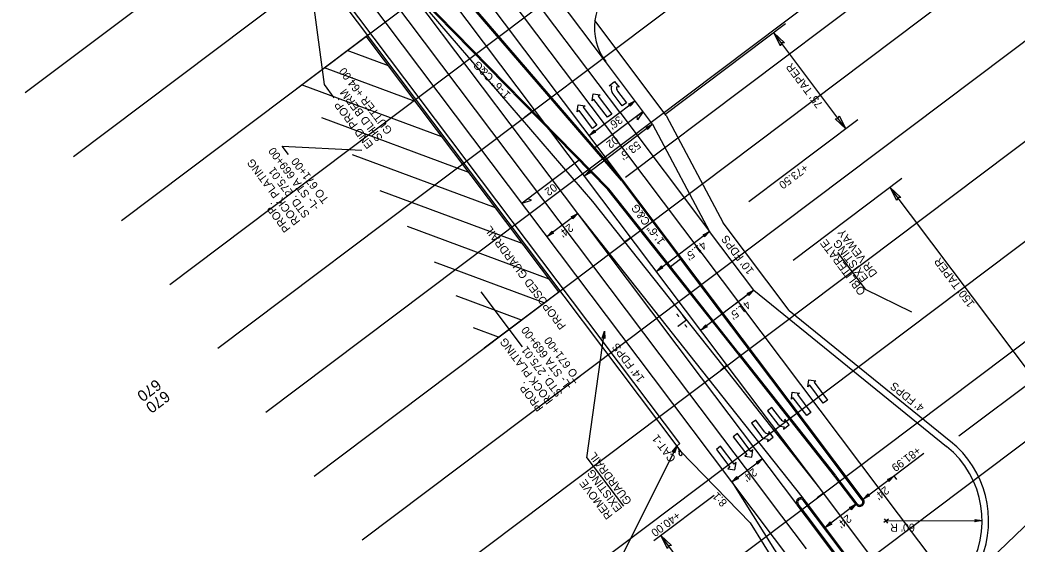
# Model space of a CAD drawing. Extents: x 1262309 to 1264352, y 775189 to 777755.
# Drawn here: x 1263383 to 1264006, y 775861 to 776189 of the extents above; entities that cross this region are included whole.
import ezdxf

# ---------------------------------------------------------------- set-up
doc = ezdxf.new("R2010")
doc.units = 0
for name, color, linetype in [('Default', 7, 'Continuous'), ('Prop Conc 1ft 6in Curb and Gutter', 7, 'Continuous'), ('Prop Conc 5in Monolithic Keyed In Island', 7, 'Continuous'), ('Prop Conc Shoulder Berm Gutter', 7, 'Continuous'), ('Prop Dimension', 7, 'Continuous'), ('Prop Dimension Text', 7, 'Continuous'), ('Prop EOT', 7, 'Continuous'), ('Prop Geotechnical Rock Plating', 7, 'Continuous'), ('Prop Guardrail', 7, 'Continuous'), ('Prop Guardrail Anchor Unit CELL', 7, 'Continuous'), ('Prop Horizontal Alignment', 7, 'Continuous'), ('Prop Horizontal Alignment Station Label', 7, 'Continuous'), ('Prop Horizontal Alignment Tick Label', 7, 'Continuous'), ('Prop Horizontal Alignment Tick Large', 7, 'Continuous'), ('Prop Horizontal Alignment Tick Small', 7, 'Continuous'), ('Prop Lane Arrow CELL', 7, 'Continuous'), ('Prop Lane Lines', 7, 'Continuous'), ('Prop Paved Shoulder', 7, 'Continuous'), ('Prop Superelevation  Arrow CELL', 7, 'Continuous'), ('Prop Superelevation Label', 7, 'Continuous'), ('Prop Terminator CELL', 7, 'Continuous'), ('Scratch_Level_3', 7, 'Continuous')]:
    doc.layers.add(name, color=color, linetype=linetype)

msp = doc.modelspace()

# ---------------------------------------------------------------- linework, layer by layer
at = {"layer": 'Default'}
for p, q in [((1263704.74, 776132.85), (1263704.74, 776132.85)), ((1263704.74, 776132.85), (1263704.74, 776132.85)), ((1263764.91, 776052.98), (1263764.91, 776052.98)), ((1263764.91, 776052.98), (1263764.91, 776052.98)), ((1263825.07, 775973.1), (1263825.07, 775973.1)), ((1263825.07, 775973.1), (1263825.07, 775973.1)), ((1263792.88, 775922.07), (1263793.52, 775922.55)), ((1263793.3, 775921.51), (1263792.88, 775922.07)), ((1263793.94, 775922), (1263792.88, 775922.07)), ((1263793.52, 775922.55), (1263793.3, 775921.51)), ((1263793.94, 775922), (1263793.3, 775921.51)), ((1263793.52, 775922.55), (1263795.65, 775919.72)), ((1263793.52, 775922.55), (1263793.94, 775922)), ((1263795.28, 775919.55), (1263794.46, 775921.31)), ((1263794.75, 775919.59), (1263795.39, 775920.07)), ((1263795.17, 775919.03), (1263794.75, 775919.59)), ((1263795.81, 775919.51), (1263794.75, 775919.59)), ((1263794.94, 775918.03), (1263795.25, 775919.09)), ((1263795.39, 775920.07), (1263795.17, 775919.03)), ((1263795.81, 775919.51), (1263795.17, 775919.03)), ((1263795.39, 775920.07), (1263795.81, 775919.51)), ((1263795.73, 775919.62), (1263795.65, 775919.72)), ((1263795.65, 775919.72), (1263796.69, 775918.35)), ((1263885.24, 775893.22), (1263885.24, 775893.22)), ((1263885.24, 775893.22), (1263885.24, 775893.22))]:
    msp.add_line(p, q, dxfattribs=at)
msp.add_ellipse((1263795.89, 775917.75), major_axis=(0.793, 0.597), ratio=0.995379, start_param=2.210226, end_param=6.283185, dxfattribs=at)
at = {"layer": 'Prop Conc 1ft 6in Curb and Gutter'}
for p, q in [((1263759.04, 776088.61), (1263638.31, 776228.96)), ((1263751.03, 776083.43), (1263620.92, 776216.3)), ((1263759.04, 776088.61), (1263795.92, 776039.64)), ((1263789.59, 776034.75), (1263751.03, 776083.43))]:
    msp.add_line(p, q, dxfattribs=at)
at = {"layer": 'Prop Conc 5in Monolithic Keyed In Island'}
for p, q in [((1263789.59, 776034.75), (1263795.92, 776039.64)), ((1263852.24, 775964.87), (1263795.93, 776039.64)), ((1263832.41, 775980.69), (1263789.6, 776034.75)), ((1263892.99, 775904.15), (1263832.43, 775980.69)), ((1263873.97, 775936.02), (1263852.24, 775964.87)), ((1263909.45, 775888.91), (1263873.97, 775936.02)), ((1263906.27, 775886.51), (1263893, 775904.13)), ((1263913.22, 775834.88), (1263872.6, 775888.8)), ((1263875.17, 775878.75), (1263869.42, 775886.39)), ((1263909.06, 775886.13), (1263909.04, 775886.11)), ((1263932.02, 775803.27), (1263875.17, 775878.75))]:
    msp.add_line(p, q, dxfattribs=at)
for centre, radius, start, end in [((1263871.04, 775887.55), 2, 38.65311, 215.6082), ((1263907.87, 775887.7), 1.99, 216.35497, 36.98742)]:
    msp.add_arc(centre, radius, start, end, dxfattribs=at)
at = {"layer": 'Prop Conc Shoulder Berm Gutter'}
for p, q in [((1263560.24, 776232.45), (1263699.52, 776047.54)), ((1263699.52, 776047.54), (1263793.48, 775922.63))]:
    msp.add_line(p, q, dxfattribs=at)
at = {"layer": 'Prop Dimension'}
for p, q in [((1263934.61, 776220.85), (1263761.55, 776090.5)), ((1263861.48, 776186.44), (1263786.12, 776129.67)), ((1263899.19, 776120.94), (1263854.09, 776180.87)), ((1263906.61, 776126.53), (1263838.59, 776075.3)), ((1263934.25, 776089.82), (1263866.24, 776038.59)), ((1264017.09, 775964.42), (1263926.84, 776084.24)), ((1263894, 776043.66), (1263911.23, 776020.7)), ((1263911.23, 776020.7), (1263940.1, 776006.46)), ((1264024.5, 775970.01), (1263969.69, 775928.73)), ((1264095.35, 775953.43), (1263984.45, 775847.18)), ((1263828.02, 775900.2), (1263847.19, 775914.64)), ((1263816.85, 775891.79), (1263779.23, 775863.45)), ((1263924.36, 775875.82), (1263923, 775874.79)), ((1263924.36, 775875.82), (1263923.33, 775877.18)), ((1263925.73, 775876.85), (1263924.36, 775875.82)), ((1263924.36, 775875.82), (1263984.36, 775876.02)), ((1263925.39, 775874.45), (1263924.36, 775875.82)), ((1263867.83, 775754.67), (1263783.48, 775866.65))]:
    msp.add_line(p, q, dxfattribs=at)
for points in [[(1263742.82, 776118.87), (1263738.77, 776116.76), (1263741.89, 776120.14), (1263741.92, 776119.15)], [(1263739.93, 776093.62), (1263735.88, 776091.52), (1263739, 776094.89), (1263739.03, 776093.91)], [(1263716.56, 776055.67), (1263712.51, 776053.56), (1263715.63, 776056.94), (1263715.66, 776055.95)], [(1263784.9, 776033.92), (1263780.85, 776031.81), (1263783.97, 776035.18), (1263784, 776034.2)], [(1263812.56, 775997.19), (1263808.5, 775995.1), (1263811.63, 775998.46), (1263811.65, 775997.48)], [(1263914.02, 775891.58), (1263909.97, 775889.47), (1263913.09, 775892.85), (1263913.11, 775891.86)], [(1263890.39, 775873.92), (1263886.34, 775871.82), (1263889.45, 775875.19), (1263889.48, 775874.21)]]:
    msp.add_lwpolyline(points, close=True, dxfattribs=at)
at = {"layer": 'Prop Dimension Text'}
for p, q in [((1263573.35, 776148.51), (1263562.13, 776233.92)), ((1263579.58, 776140.3), (1263573.35, 776148.51)), ((1263738.77, 776116.76), (1263767.53, 776138.42)), ((1263778.46, 776123.9), (1263735.88, 776091.52)), ((1263551.05, 776104.85), (1263547.06, 776110.14)), ((1263547.06, 776110.14), (1263596.68, 776107.56)), ((1263731.68, 776068), (1263712.51, 776053.56)), ((1263814, 776056.77), (1263780.85, 776031.81)), ((1263697.25, 775984.73), (1263671.36, 776018.93)), ((1263839.65, 776018.57), (1263808.5, 775995.1)), ((1263841.65, 776020.07), (1263829.72, 776011.09)), ((1263737.43, 775915.28), (1263748.39, 775994.46)), ((1263793.48, 775922.63), (1263759.14, 775854)), ((1263909.97, 775889.47), (1263947.96, 775918.09)), ((1263737.43, 775915.28), (1263760.26, 775884.99)), ((1263929.07, 775904), (1263930.72, 775901.82)), ((1263905.51, 775886.26), (1263886.34, 775871.82))]:
    msp.add_line(p, q, dxfattribs=at)
for points in [[(1263858.27, 776172.75), (1263854.09, 776180.87), (1263860.82, 776174.6), (1263858.85, 776174.56)], [(1263763.48, 776136.31), (1263767.53, 776138.42), (1263764.41, 776135.04), (1263764.39, 776136.03)], [(1263774.41, 776121.8), (1263778.46, 776123.9), (1263775.35, 776120.53), (1263775.32, 776121.51)], [(1263895.02, 776129.07), (1263899.19, 776120.94), (1263892.47, 776127.21), (1263894.44, 776127.25)], [(1263895.02, 776129.07), (1263899.19, 776120.94), (1263892.47, 776127.21), (1263894.44, 776127.25)], [(1263931.02, 776076.12), (1263926.84, 776084.24), (1263933.56, 776077.98), (1263931.59, 776077.93)], [(1263727.63, 776065.89), (1263731.68, 776068), (1263728.57, 776064.62), (1263728.54, 776065.61)], [(1263809.95, 776054.67), (1263814, 776056.78), (1263810.88, 776053.4), (1263810.86, 776054.38)], [(1263837.59, 776017.98), (1263841.65, 776020.07), (1263838.51, 776016.71), (1263838.49, 776017.7)], [(1263844.06, 775911.32), (1263847.19, 775914.64), (1263843.1, 775912.56), (1263844.04, 775912.27)], [(1263832.08, 775902.29), (1263828.02, 775900.2), (1263831.16, 775903.57), (1263831.18, 775902.58)], [(1263925.09, 775901.81), (1263929.14, 775903.91), (1263926.02, 775900.54), (1263926, 775901.52)], [(1263901.46, 775884.15), (1263905.51, 775886.26), (1263902.39, 775882.88), (1263902.36, 775883.87)], [(1263787.66, 775858.53), (1263783.48, 775866.65), (1263790.2, 775860.39), (1263788.23, 775860.34)]]:
    msp.add_lwpolyline(points, close=True, dxfattribs=at)
at = {"layer": 'Prop EOT'}
for p, q in [((1263710.7, 776055.96), (1263423.46, 776437.32)), ((1263759.64, 776089.06), (1263638.9, 776229.42)), ((1263750.5, 776082.9), (1263620.38, 776215.77)), ((1263778.46, 776123.9), (1263749.05, 776162.96)), ((1263778.46, 776123.9), (1263814, 776056.78)), ((1263852.84, 775965.32), (1263759.64, 776089.06)), ((1263831.82, 775980.22), (1263750.5, 776082.9)), ((1263778.98, 775965.32), (1263710.7, 776055.96)), ((1263841.65, 776020.07), (1263814, 776056.78)), ((1263841.65, 776020.07), (1263962.14, 775922.43)), ((1263892.39, 775903.67), (1263831.83, 775980.21)), ((1263828.02, 775900.2), (1263778.98, 775965.32)), ((1263874.57, 775936.47), (1263852.84, 775965.32)), ((1263910.05, 775889.36), (1263874.57, 775936.47)), ((1263828.02, 775900.2), (1263902.67, 775781.16)), ((1263905.66, 775886.06), (1263892.39, 775903.67)), ((1263874.57, 775887.44), (1263873.2, 775889.25)), ((1263913.82, 775835.33), (1263874.57, 775887.44)), ((1263874.57, 775878.3), (1263868.82, 775885.94)), ((1263931.42, 775802.82), (1263874.57, 775878.3))]:
    msp.add_line(p, q, dxfattribs=at)
for centre, radius, start, end in [((1263777.07, 776183.93), 35, 127.94574, 216.98742), ((1263924.36, 775875.82), 60, 327.25458, 50.98263), ((1263871.01, 775887.59), 2.75, 126.98742, 216.98742), ((1263871.01, 775887.6), 2.74, 36.98742, 126.98742), ((1263907.86, 775887.72), 2.74, 306.98742, 36.98742), ((1263907.85, 775887.7), 2.74, 216.98742, 306.98742)]:
    msp.add_arc(centre, radius, start, end, dxfattribs=at)
at = {"layer": 'Prop Geotechnical Rock Plating'}
for p, q in [((1263556.16, 776146.13), (1263599.45, 776178.74)), ((1263719.76, 776018.97), (1263599.45, 776178.74)), ((1263613.36, 776160.26), (1263587.62, 776169.82)), ((1263630.08, 776138.05), (1263573.39, 776159.11)), ((1263646.81, 776115.84), (1263559.16, 776148.39)), ((1263663.54, 776093.63), (1263571.7, 776127.73)), ((1263680.26, 776071.42), (1263591.01, 776104.56)), ((1263696.99, 776049.21), (1263608.14, 776082.2)), ((1263713.72, 776026.99), (1263625.22, 776059.85)), ((1263710.67, 776012.12), (1263642.25, 776037.53)), ((1263673.29, 775983.97), (1263719.76, 776018.97)), ((1263696.44, 776001.41), (1263655.62, 776016.56)), ((1263682.13, 775990.72), (1263666.48, 775996.53))]:
    msp.add_line(p, q, dxfattribs=at)
at = {"layer": 'Prop Guardrail'}
for p, q in [((1263502.31, 776309.36), (1263699.52, 776047.54)), ((1263699.52, 776047.54), (1263793.48, 775922.63))]:
    msp.add_line(p, q, dxfattribs=at)
at = {"layer": 'Prop Horizontal Alignment'}
for p, q in [((1263830.93, 775965.32), (1263334.24, 776624.75)), ((1263874.57, 775907.39), (1263830.93, 775965.32)), ((1264143.94, 775549.75), (1263874.57, 775907.39))]:
    msp.add_line(p, q, dxfattribs=at)
at = {"layer": 'Prop Horizontal Alignment Tick Large'}
msp.add_line((1263704.74, 776132.85), (1263698.35, 776128.04), dxfattribs=at)
at = {"layer": 'Prop Horizontal Alignment Tick Small'}
for p, q in [((1263764.91, 776052.98), (1263760.92, 776049.97)), ((1263825.07, 775973.1), (1263821.08, 775970.09)), ((1263885.23, 775893.22), (1263881.24, 775890.22))]:
    msp.add_line(p, q, dxfattribs=at)
at = {"layer": 'Prop Lane Arrow CELL'}
for p, q in [((1263751.24, 776147.83), (1263754.73, 776150.52)), ((1263754.73, 776150.52), (1263757.47, 776146.95)), ((1263740.62, 776138.42), (1263741.2, 776142.8)), ((1263741.2, 776142.8), (1263745.65, 776142.21)), ((1263752.71, 776147.62), (1263751.24, 776147.83)), ((1263759.46, 776135.18), (1263753.11, 776143.61)), ((1263757.47, 776146.95), (1263756, 776147.16)), ((1263756.59, 776144.47), (1263762.09, 776137.16)), ((1263741.82, 776139.32), (1263740.62, 776138.42)), ((1263750.24, 776128.14), (1263741.82, 776139.32)), ((1263745.65, 776142.21), (1263744.46, 776141.31)), ((1263744.46, 776141.31), (1263752.88, 776130.12)), ((1263762.09, 776137.16), (1263759.46, 776135.18)), ((1263731.28, 776131.48), (1263731.86, 776135.86)), ((1263732.47, 776132.38), (1263731.28, 776131.48)), ((1263731.86, 776135.86), (1263736.31, 776135.27)), ((1263740.9, 776121.2), (1263732.47, 776132.38)), ((1263736.31, 776135.27), (1263735.11, 776134.37)), ((1263735.11, 776134.37), (1263743.53, 776123.18)), ((1263752.88, 776130.12), (1263750.24, 776128.14)), ((1263743.53, 776123.18), (1263740.9, 776121.2)), ((1263875.48, 775959.7), (1263876.06, 775964.09)), ((1263876.06, 775964.09), (1263880.51, 775963.49)), ((1263880.51, 775963.49), (1263879.32, 775962.59)), ((1263879.32, 775962.59), (1263887.74, 775951.41)), ((1263865.13, 775951.91), (1263865.71, 775956.29)), ((1263865.71, 775956.29), (1263870.16, 775955.7)), ((1263870.16, 775955.7), (1263868.96, 775954.79)), ((1263876.68, 775960.61), (1263875.48, 775959.7)), ((1263885.1, 775949.42), (1263876.68, 775960.61)), ((1263866.33, 775952.81), (1263865.13, 775951.91)), ((1263874.75, 775941.63), (1263866.33, 775952.81)), ((1263868.96, 775954.79), (1263877.39, 775943.61)), ((1263887.74, 775951.41), (1263885.1, 775949.42)), ((1263852.94, 775946.67), (1263850.31, 775944.68)), ((1263850.31, 775944.68), (1263856.65, 775936.26)), ((1263858.45, 775939.36), (1263852.94, 775946.67)), ((1263877.39, 775943.61), (1263874.75, 775941.63)), ((1263842.87, 775938.91), (1263840.23, 775936.92)), ((1263840.23, 775936.92), (1263846.58, 775928.5)), ((1263848.38, 775931.6), (1263842.87, 775938.91)), ((1263861.08, 775939.53), (1263860.87, 775938.06)), ((1263863.74, 775935.9), (1263861.08, 775939.53)), ((1263851.01, 775931.77), (1263850.8, 775930.3)), ((1263853.67, 775928.14), (1263851.01, 775931.77)), ((1263860.2, 775933.29), (1263863.74, 775935.9)), ((1263860.41, 775934.77), (1263860.2, 775933.29)), ((1263831.42, 775930.46), (1263828.78, 775928.47)), ((1263828.78, 775928.47), (1263837.21, 775917.29)), ((1263839.84, 775919.28), (1263831.42, 775930.46)), ((1263850.13, 775925.53), (1263853.67, 775928.14)), ((1263850.33, 775927), (1263850.13, 775925.53)), ((1263820.95, 775922.57), (1263818.31, 775920.58)), ((1263818.31, 775920.58), (1263826.73, 775909.4)), ((1263829.37, 775911.39), (1263820.95, 775922.57)), ((1263841.04, 775920.18), (1263839.84, 775919.28)), ((1263840.38, 775915.74), (1263841.04, 775920.18)), ((1263830.57, 775912.29), (1263829.37, 775911.39)), ((1263829.91, 775907.85), (1263830.57, 775912.29)), ((1263837.21, 775917.29), (1263836.01, 775916.39)), ((1263836.01, 775916.39), (1263840.38, 775915.74)), ((1263826.73, 775909.4), (1263825.53, 775908.5)), ((1263825.53, 775908.5), (1263829.91, 775907.85))]:
    msp.add_line(p, q, dxfattribs=at)
for centre, radius, start, end in [((1263757.72, 776146.09), 5.25, 162.99965, 208.31134), ((1263759.18, 776146.44), 3.27, 167.32924, 216.98742), ((1263861.06, 775941.31), 3.27, 216.98742, 266.64559), ((1263850.98, 775933.55), 3.27, 216.98742, 266.64559), ((1263860.31, 775940), 5.25, 225.66349, 270.97518), ((1263850.24, 775932.24), 5.25, 225.66349, 270.97518)]:
    msp.add_arc(centre, radius, start, end, dxfattribs=at)
at = {"layer": 'Prop Lane Lines'}
for p, q in [((1263794, 775965.32), (1263433.04, 776444.54)), ((1263749.05, 776162.96), (1263688.78, 776242.97)), ((1263759.64, 776089.06), (1263648.34, 776236.82)), ((1263757.94, 776131.2), (1263685.9, 776226.85)), ((1263748.36, 776123.98), (1263676.32, 776219.63)), ((1263731.68, 776068), (1263620.38, 776215.77)), ((1263741.09, 776075.45), (1263620.38, 776215.77)), ((1263757.94, 776131.2), (1263814, 776056.78)), ((1263968.96, 775831.09), (1263748.36, 776123.98)), ((1263822.42, 775972.77), (1263741.09, 776075.45)), ((1263809.02, 775965.32), (1263731.68, 776068)), ((1263882.89, 775896.34), (1263822.42, 775972.77)), ((1263836.43, 775908.99), (1263794, 775965.32)), ((1263868.55, 775886.29), (1263809.02, 775965.32)), ((1263859.23, 775878.72), (1263836.43, 775908.99)), ((1263871.74, 775842.16), (1263828.02, 775900.2)), ((1263896.07, 775878.84), (1263882.89, 775896.34)), ((1263874.57, 775858.35), (1263859.23, 775878.72))]:
    msp.add_line(p, q, dxfattribs=at)
for points in [[(1263813.01, 775965.32), (1263731.68, 776068)], [(1263872.65, 775889.93), (1263813.01, 775965.32)]]:
    msp.add_lwpolyline(points, dxfattribs=at)
at = {"layer": 'Prop Paved Shoulder'}
for p, q in [((1263795.48, 775924.14), (1263562.13, 776233.92)), ((1263786.93, 776129.29), (1263742.3, 776188.54)), ((1263786.93, 776129.29), (1263822.47, 776062.16)), ((1263863.82, 776007.25), (1263822.47, 776062.16)), ((1263863.82, 776007.25), (1263964.66, 775925.54)), ((1263795.48, 775924.14), (1263793.48, 775922.63)), ((1263795.81, 775919.51), (1263839.29, 775874.67)), ((1263839.29, 775874.67), (1263899.47, 775778.75))]:
    msp.add_line(p, q, dxfattribs=at)
msp.add_arc((1263924.36, 775875.82), 64, 337.81209, 50.98071, dxfattribs=at)
at = {"layer": 'Prop Superelevation  Arrow CELL'}
for p, q in [((1263772.56, 776131.74), (1263742.44, 776109.05)), ((1263732.56, 776101.22), (1263696.86, 776074.34))]:
    msp.add_line(p, q, dxfattribs=at)
for points in [[(1263772.56, 776131.74), (1263768.97, 776126.53), (1263768.87, 776128.95)], [(1263696.86, 776074.34), (1263702.86, 776076.35), (1263700.56, 776077.12)]]:
    msp.add_lwpolyline(points, close=True, dxfattribs=at)
at = {"layer": 'Prop Terminator CELL'}
for points in [[(1263747, 775990.11), (1263748.39, 775994.46), (1263748.56, 775989.87), (1263747.85, 775990.55)], [(1263790.74, 775918.98), (1263793.49, 775922.62), (1263792.12, 775918.23), (1263791.68, 775919.11)], [(1263979.86, 775876.78), (1263984.36, 775876.02), (1263979.84, 775875.21), (1263980.41, 775876.01)]]:
    msp.add_lwpolyline(points, close=True, dxfattribs=at)
at = {"layer": 'Scratch_Level_3'}
for p, q in [((1263386.48, 776143.52), (1263881.58, 776516.43)), ((1263416.56, 776103.58), (1263911.66, 776476.49)), ((1263446.64, 776063.64), (1263941.74, 776436.56)), ((1263476.73, 776023.7), (1263971.83, 776396.62)), ((1263506.81, 775983.76), (1264001.91, 776356.68)), ((1263536.89, 775943.83), (1264031.99, 776316.74)), ((1263566.97, 775903.89), (1264062.07, 776276.8)), ((1263597.05, 775863.95), (1264092.15, 776236.86)), ((1263627.14, 775824.01), (1264122.24, 776196.93)), ((1263657.22, 775784.07), (1264152.32, 776156.99)), ((1263687.3, 775744.13), (1264182.4, 776117.05)), ((1263717.38, 775704.2), (1264212.48, 776077.11))]:
    msp.add_line(p, q, dxfattribs=at)

# ---------------------------------------------------------------- texts
at = {"layer": 'Prop Dimension'}
msp.add_text('1\'-6" C&G', height=5, rotation=134.22343, dxfattribs=at).set_placement((1263690.1, 776142.54))
at = {"layer": 'Prop Dimension Text'}
for s, rotation, p in [("75' TAPER", 126.98742, (1263885.08, 776136.24)), ('GUTTER +64.00', 126.98742, (1263616.15, 776119.79)), ('SHLD BERM', 126.98742, (1263610.16, 776115.28)), ('END PROP.', 126.98742, (1263604.17, 776110.77)), ("36'", 217.25838, (1263757.35, 776129.34)), ("53.5'", 217.25838, (1263768.67, 776113.6)), ('-L- STA 669+00', 126.98742, (1263570.48, 776072.03)), ('ROCK PLATING', 126.98742, (1263558.49, 776063)), ('TO 671+00', 126.98742, (1263576.47, 776076.54)), ('STD. 275.01', 126.98742, (1263564.49, 776067.51)), ('+73.50', 216.98742, (1263873.33, 776099.29)), ('PROP.', 126.98742, (1263552.5, 776058.49)), ('1\'-6" C&G', 126.98742, (1263786.41, 776050.76)), ("24'", 217.25838, (1263726.53, 776061.87)), ('DRIVEWAY', 126.98742, (1263919.15, 776030.48)), ("41.5'", 217.25838, (1263809.79, 776050.92)), ("10' FDPS", 126.98742, (1263842, 776032.25)), ('OBLITERATE', 126.98742, (1263911.8, 776019.17)), ('EXISTING', 126.98742, (1263913.47, 776027.48)), ("150' TAPER", 126.98742, (1263979.92, 776011.71)), ("41.5'", 216.98777, (1263837.41, 776013.84)), ('-L- STA 669+00', 126.98742, (1263728.45, 775960.11)), ('ROCK PLATING', 126.98742, (1263716.46, 775951.09)), ('TO 671+00', 126.98742, (1263734.44, 775964.62)), ("14' FDPS", 126.98742, (1263773.7, 775964.84)), ('STD. 275.01', 126.98742, (1263722.46, 775955.6)), ('PROP.', 126.98742, (1263710.47, 775946.58)), ("4' FDPS", 140.98263, (1263948.63, 775947.45)), ('GUARDRAIL', 126.98742, (1263765.75, 775888.23)), ('+81.99', 216.98742, (1263943.7, 775922.64)), ('EXISTING', 126.98742, (1263759.76, 775883.72)), ("24'", 216.71645, (1263841.39, 775909.1)), ('REMOVE', 126.98742, (1263753.77, 775879.21)), ('8:1', 134.11243, (1263825.37, 775887.59)), ("24'", 217.25838, (1263923.83, 775897.82)), ('+40.00', 216.98742, (1263793.49, 775881.99)), ("24'", 217.25838, (1263900.35, 775880.13)), ("60' R", 180.19536, (1263942.29, 775874.13))]:
    msp.add_text(s, height=5, rotation=rotation, dxfattribs=at).set_placement(p)
at = {"layer": 'Prop Guardrail Anchor Unit CELL'}
for s, p in [('PROPOSED GUARDRAIL', (1263724.63, 775997.77)), ('CAT-1', (1263793.29, 775914.87))]:
    msp.add_text(s, height=5, rotation=126.98742, dxfattribs=at).set_placement(p)
at = {"layer": 'Prop Horizontal Alignment Station Label'}
msp.add_text('-L-', height=7, rotation=126.98742, dxfattribs=at).set_placement((1263802.32, 775998.09))
at = {"layer": 'Prop Horizontal Alignment Tick Label'}
for p in [(1263468.15, 775964.84), (1263473.61, 775957.67)]:
    msp.add_text('670', height=7, rotation=216.98742, dxfattribs=at).set_placement(p)
at = {"layer": 'Prop Superelevation Label'}
for p in [(1263754.93, 776116.75), (1263716.42, 776087.08)]:
    msp.add_text('02', height=5, rotation=216.98742, dxfattribs=at).set_placement(p)

doc.saveas('drawing.dxf')
